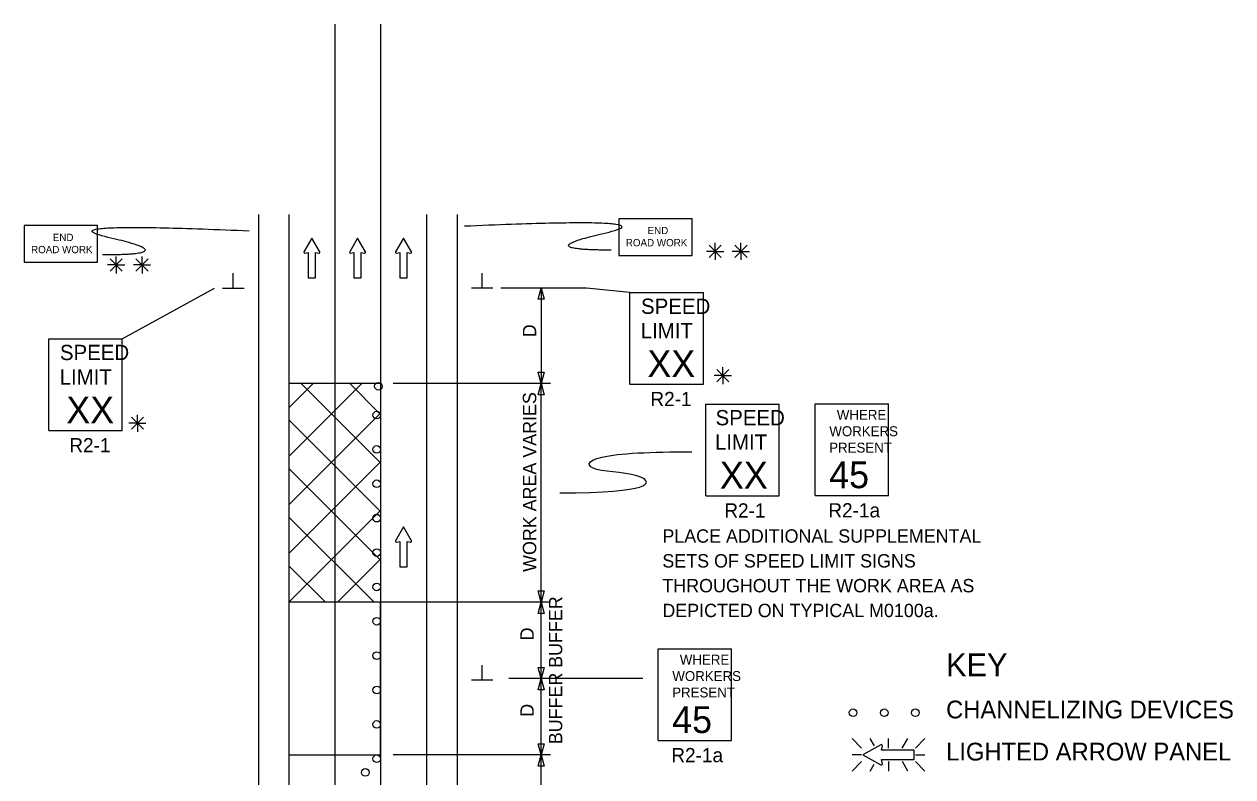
# Model space of a CAD drawing. Extents: x 16553 to 18475, y 5759 to 7026.
# Drawn here: x 16749 to 17382, y 6632 to 7026 of the extents above; entities that cross this region are included whole.
import ezdxf

# ---------------------------------------------------------------- set-up
doc = ezdxf.new("R2010")
doc.units = 0
for name, color, linetype in [('ALI_LEGAL_EX', 7, 'Continuous'), ('MT_SCRATCH_LEVEL_A', 7, 'Continuous'), ('MT_SCRATCH_LEVEL_E', 7, 'Continuous'), ('PAVT_EDGE_EX', 7, 'Continuous'), ('TRAFFIC_SIGNS_PR', 7, 'Continuous'), ('TYPICAL_TEXT_DIMEN_EX', 7, 'Continuous'), ('TYPICAL_TEXT_DIMEN_PR', 7, 'Continuous')]:
    doc.layers.add(name, color=color, linetype=linetype)

msp = doc.modelspace()

# ---------------------------------------------------------------- linework, layer by layer
at = {"layer": 'ALI_LEGAL_EX'}
for p, q in [((16911.66, 7026.35), (16911.66, 6197.16)), ((16935.66, 7026.35), (16935.66, 6197.16)), ((16935.66, 7026.35), (16935.66, 6197.16))]:
    msp.add_line(p, q, dxfattribs=at)
for points in [[(16911.66, 6926.35), (16911.66, 6901.35)], [(16935.66, 6926.35), (16935.66, 6901.35)], [(16911.66, 6826.35), (16911.66, 6801.35)], [(16935.66, 6826.35), (16935.66, 6801.35)], [(16911.66, 6726.35), (16911.66, 6701.35)], [(16935.66, 6726.35), (16935.66, 6701.35)]]:
    msp.add_lwpolyline(points, dxfattribs=at)
at = {"layer": 'MT_SCRATCH_LEVEL_A'}
msp.add_line((16935.66, 6838.16), (16887.66, 6838.16), dxfattribs=at)
at = {"layer": 'MT_SCRATCH_LEVEL_E'}
for p, q in [((16899.66, 6914.3), (16895.55, 6907.06)), ((16903.81, 6907.06), (16899.66, 6914.3)), ((16923.57, 6914.3), (16919.46, 6907.06)), ((16927.71, 6907.06), (16923.57, 6914.3)), ((16947.62, 6914.3), (16943.51, 6907.06)), ((16951.77, 6907.06), (16947.62, 6914.3)), ((16896.03, 6906.37), (16897.81, 6906.69)), ((16897.81, 6906.69), (16897.81, 6893.43)), ((16901.55, 6893.43), (16901.55, 6906.69)), ((16901.55, 6906.69), (16903.33, 6906.37)), ((16919.94, 6906.37), (16921.72, 6906.69)), ((16921.72, 6906.69), (16921.72, 6893.43)), ((16925.46, 6893.43), (16925.46, 6906.69)), ((16925.46, 6906.69), (16927.23, 6906.37)), ((16943.99, 6906.37), (16945.77, 6906.69)), ((16945.77, 6906.69), (16945.77, 6893.43)), ((16949.51, 6893.43), (16949.51, 6906.69)), ((16949.51, 6906.69), (16951.29, 6906.37)), ((16897.81, 6893.43), (16901.55, 6893.43)), ((16921.72, 6893.43), (16925.46, 6893.43)), ((16945.77, 6893.43), (16949.51, 6893.43)), ((16947.62, 6763.02), (16943.51, 6755.78)), ((16951.77, 6755.78), (16947.62, 6763.02)), ((16943.99, 6755.1), (16945.77, 6755.41)), ((16945.77, 6755.41), (16945.77, 6742.15)), ((16949.51, 6742.15), (16949.51, 6755.41)), ((16949.51, 6755.41), (16951.29, 6755.1)), ((16945.77, 6742.15), (16949.51, 6742.15))]:
    msp.add_line(p, q, dxfattribs=at)
for centre, start, end in [((16895.96, 6906.83), 150.42484, 279.96381), ((16903.4, 6906.83), 260.03619, 29.77312), ((16919.86, 6906.83), 150.42484, 279.96381), ((16927.3, 6906.83), 260.03619, 29.77312), ((16943.92, 6906.83), 150.42484, 279.96381), ((16951.36, 6906.83), 260.03619, 29.77312), ((16943.92, 6755.56), 150.42484, 279.96381), ((16951.36, 6755.56), 260.03619, 29.77312)]:
    msp.add_arc(centre, 0.463, start, end, dxfattribs=at)
at = {"layer": 'PAVT_EDGE_EX'}
for p, q in [((16871.66, 6926.66), (16871.66, 6280.21)), ((16887.66, 6926.66), (16887.66, 6280.21)), ((16959.66, 6926.66), (16959.66, 6280.21)), ((16975.66, 6926.66), (16975.66, 6280.21)), ((16935.66, 6838.16), (16887.66, 6838.16)), ((16887.66, 6838.16), (16887.66, 6723.62)), ((16887.66, 6825.45), (16900.38, 6838.16)), ((16887.66, 6799.99), (16925.83, 6838.16)), ((16935.66, 6796.54), (16894.04, 6838.16)), ((16935.66, 6822), (16919.5, 6838.16)), ((16887.66, 6774.54), (16935.66, 6822.54)), ((16935.66, 6771.08), (16887.66, 6819.08)), ((16887.66, 6749.08), (16935.66, 6797.08)), ((16935.66, 6745.63), (16887.66, 6793.63)), ((16887.66, 6723.62), (16935.66, 6771.62)), ((16932.21, 6723.62), (16887.66, 6768.17)), ((16913.12, 6723.62), (16935.66, 6746.17)), ((16906.76, 6723.62), (16887.66, 6742.72)), ((16887.66, 6643.62), (16935.66, 6643.62))]:
    msp.add_line(p, q, dxfattribs=at)
msp.add_lwpolyline([(16935.66, 6723.62), (16887.66, 6723.62), (16887.66, 6643.62), (16935.66, 6643.62)], close=True, dxfattribs=at)
at = {"layer": 'TRAFFIC_SIGNS_PR'}
for p, q in [((17066.18, 6885.75), (17104.58, 6885.75)), ((17066.18, 6837.75), (17066.18, 6885.75)), ((17104.58, 6837.75), (17104.58, 6885.75)), ((16762.02, 6861.55), (16800.42, 6861.55)), ((16762.02, 6813.55), (16762.02, 6861.55)), ((16800.42, 6813.55), (16800.42, 6861.55)), ((17066.18, 6837.75), (17104.58, 6837.75)), ((17105.94, 6827.39), (17144.34, 6827.39)), ((17105.94, 6779.39), (17105.94, 6827.39)), ((17144.34, 6779.39), (17144.34, 6827.39)), ((17163.13, 6827.47), (17201.53, 6827.47)), ((17163.13, 6779.47), (17163.13, 6827.47)), ((17201.53, 6779.47), (17201.53, 6827.47)), ((16762.02, 6813.55), (16800.42, 6813.55)), ((17105.94, 6779.39), (17144.34, 6779.39)), ((17163.13, 6779.47), (17201.53, 6779.47)), ((17080.96, 6699.25), (17119.36, 6699.25)), ((17080.96, 6651.25), (17080.96, 6699.25)), ((17119.36, 6651.25), (17119.36, 6699.25)), ((17080.96, 6651.25), (17119.36, 6651.25)), ((17182.39, 6652.17), (17187.32, 6647.24)), ((17194.15, 6648.35), (17191.94, 6652.17)), ((17201.47, 6647.24), (17201.47, 6652.17)), ((17208.7, 6647.24), (17211.55, 6652.17)), ((17215.62, 6647.24), (17220.55, 6652.17)), ((17187.32, 6643.68), (17182.39, 6643.68)), ((17215.62, 6643.68), (17220.55, 6643.68)), ((17182.39, 6635.19), (17187.32, 6640.13)), ((17191.9, 6635.19), (17194.01, 6638.85)), ((17201.47, 6640.13), (17201.47, 6635.19)), ((17211.6, 6635.19), (17208.75, 6640.13)), ((17215.62, 6640.13), (17220.55, 6635.19))]:
    msp.add_line(p, q, dxfattribs=at)
for points in [[(17060.4, 6905.24), (17098.8, 6905.24), (17098.8, 6924.44), (17060.4, 6924.44)], [(16749.09, 6901.65), (16787.49, 6901.65), (16787.49, 6920.85), (16749.09, 6920.85)]]:
    msp.add_lwpolyline(points, close=True, dxfattribs=at)
for points in [[(17197.4, 6648.96), (17188.1, 6643.68), (17197.4, 6638.36)], [(17198.27, 6638.99), (17197.87, 6641.26), (17214.88, 6641.26), (17214.88, 6646.06), (17197.87, 6646.06), (17198.27, 6648.34)]]:
    msp.add_lwpolyline(points, dxfattribs=at)
for centre in [(16934.48, 6836.73), (16933.66, 6821.62), (16933.66, 6803.62), (16933.66, 6785.62), (16933.66, 6767.62), (16933.66, 6749.62), (16933.66, 6731.62), (16933.66, 6713.62), (16933.66, 6695.62), (16933.66, 6677.62), (16933.66, 6659.62), (17182.95, 6665.71), (17199.25, 6665.71), (17215.55, 6665.71), (16933.66, 6641.62), (16927.66, 6634.48)]:
    msp.add_circle(centre, 2, dxfattribs=at)
for centre, radius, start, end in [((17197.68, 6648.43), 0.598, 350.73078, 118.89165), ((17197.68, 6638.88), 0.597, 241.48329, 9.95933)]:
    msp.add_arc(centre, radius, start, end, dxfattribs=at)
for points in [[(17056.4, 6908), (17013.89, 6908), (17090.41, 6925.41), (16979.62, 6920.47)], [(16790.14, 6905.64), (16832.65, 6905.64), (16756.13, 6923.05), (16866.92, 6918.11)]]:
    msp.add_open_spline(points, degree=2, dxfattribs=at)
at = {"layer": 'TYPICAL_TEXT_DIMEN_PR'}
for p, q in [((17107.55, 6910.56), (17113.93, 6904.18)), ((17113.93, 6910.56), (17107.55, 6904.18)), ((17110.74, 6907.37), (17110.74, 6911.82)), ((17121.06, 6910.56), (17127.43, 6904.18)), ((17127.43, 6910.56), (17121.06, 6904.18)), ((17124.24, 6907.37), (17124.24, 6911.82)), ((16794.08, 6903.41), (16800.45, 6897.03)), ((16800.45, 6903.41), (16794.08, 6897.03)), ((16797.26, 6900.22), (16797.26, 6904.68)), ((16807.58, 6903.41), (16813.96, 6897.03)), ((16813.96, 6903.41), (16807.58, 6897.03)), ((16810.77, 6900.22), (16810.77, 6904.68)), ((17110.74, 6907.37), (17106.21, 6907.37)), ((17110.74, 6907.37), (17113.93, 6907.37)), ((17110.74, 6907.37), (17115.22, 6907.37)), ((17110.74, 6907.37), (17110.74, 6902.87)), ((17124.24, 6907.37), (17119.71, 6907.37)), ((17124.24, 6907.37), (17127.43, 6907.37)), ((17124.24, 6907.37), (17128.72, 6907.37)), ((17124.24, 6907.37), (17124.24, 6902.87)), ((16797.26, 6900.22), (16792.73, 6900.22)), ((16797.26, 6900.22), (16800.45, 6900.22)), ((16797.26, 6900.22), (16801.74, 6900.22)), ((16797.26, 6900.22), (16797.26, 6895.72)), ((16810.77, 6900.22), (16806.24, 6900.22)), ((16810.77, 6900.22), (16813.96, 6900.22)), ((16810.77, 6900.22), (16815.25, 6900.22)), ((16810.77, 6900.22), (16810.77, 6895.72)), ((16858.54, 6888.16), (16858.54, 6895.95)), ((16988.79, 6888.16), (16988.79, 6895.95)), ((16800.42, 6861.55), (16848.66, 6888.16)), ((16852.91, 6888.16), (16864.16, 6888.16)), ((16994.41, 6888.16), (16983.16, 6888.16)), ((17043.4, 6888.16), (16998.66, 6888.16)), ((17018.09, 6882.3), (17019.66, 6888.16)), ((17019.66, 6888.16), (17019.66, 6838.16)), ((17019.66, 6888.16), (17021.23, 6882.3)), ((17066.18, 6885.75), (17043.4, 6888.16)), ((17019.66, 6882.3), (17018.09, 6882.3)), ((17021.23, 6882.3), (17019.66, 6882.3)), ((17111.6, 6845.45), (17117.97, 6839.07)), ((17117.97, 6845.45), (17111.6, 6839.07)), ((17114.79, 6842.26), (17114.79, 6846.71)), ((17019.66, 6838.16), (17018.09, 6844.02)), ((17018.09, 6844.02), (17019.66, 6844.02)), ((17019.66, 6844.02), (17021.23, 6844.02)), ((17021.23, 6844.02), (17019.66, 6838.16)), ((17114.79, 6842.26), (17110.26, 6842.26)), ((17114.79, 6842.26), (17117.97, 6842.26)), ((17114.79, 6842.26), (17119.26, 6842.26)), ((17114.79, 6842.26), (17114.79, 6837.76)), ((17024.66, 6838.16), (16942.27, 6838.16)), ((17018.09, 6832.3), (17019.66, 6838.16)), ((17019.66, 6723.62), (17019.66, 6838.16)), ((17019.66, 6838.16), (17021.23, 6832.3)), ((17019.66, 6832.3), (17018.09, 6832.3)), ((17021.23, 6832.3), (17019.66, 6832.3)), ((16805.19, 6820.53), (16811.56, 6814.15)), ((16811.56, 6820.53), (16805.19, 6814.15)), ((16808.38, 6817.34), (16808.38, 6821.8)), ((16808.38, 6817.34), (16803.84, 6817.34)), ((16808.38, 6817.34), (16811.56, 6817.34)), ((16808.38, 6817.34), (16812.85, 6817.34)), ((16808.38, 6817.34), (16808.38, 6812.84)), ((17019.66, 6723.62), (17018.09, 6729.49)), ((17018.09, 6729.49), (17019.66, 6729.49)), ((17019.66, 6729.49), (17021.23, 6729.49)), ((17021.23, 6729.49), (17019.66, 6723.62)), ((17024.66, 6723.62), (16935.66, 6723.62)), ((17018.09, 6717.76), (17019.66, 6723.62)), ((17019.66, 6683.62), (17019.66, 6723.62)), ((17019.66, 6723.62), (17021.23, 6717.76)), ((17019.66, 6717.76), (17018.09, 6717.76)), ((17021.23, 6717.76), (17019.66, 6717.76)), ((16988.79, 6682.78), (16988.79, 6690.56)), ((17019.66, 6683.62), (17018.09, 6689.49)), ((17018.09, 6689.49), (17019.66, 6689.49)), ((17019.66, 6689.49), (17021.23, 6689.49)), ((17021.23, 6689.49), (17019.66, 6683.62)), ((16994.41, 6682.78), (16983.16, 6682.78)), ((17072.97, 6683.62), (17002.68, 6683.62)), ((17018.09, 6677.76), (17019.66, 6683.62)), ((17019.66, 6643.62), (17019.66, 6683.62)), ((17019.66, 6683.62), (17021.23, 6677.76)), ((17019.66, 6677.76), (17018.09, 6677.76)), ((17021.23, 6677.76), (17019.66, 6677.76)), ((17019.66, 6643.62), (17018.09, 6649.49)), ((17018.09, 6649.49), (17019.66, 6649.49)), ((17019.66, 6649.49), (17021.23, 6649.49)), ((17021.23, 6649.49), (17019.66, 6643.62)), ((17024.66, 6643.62), (16942.27, 6643.62)), ((17018.09, 6637.76), (17019.66, 6643.62)), ((17019.66, 6613.06), (17019.66, 6643.62)), ((17019.66, 6643.62), (17021.23, 6637.76)), ((17019.66, 6637.76), (17018.09, 6637.76)), ((17021.23, 6637.76), (17019.66, 6637.76))]:
    msp.add_line(p, q, dxfattribs=at)
msp.add_open_spline([(17029.51, 6780.89), (17077.98, 6780.89), (17077.98, 6791.65), (17043.06, 6791.65), (17043.06, 6800.7), (17077.26, 6802.46), (17098.55, 6802.36)], degree=3, dxfattribs=at)

# ---------------------------------------------------------------- texts
at = {"layer": 'TRAFFIC_SIGNS_PR'}
for s, height, p in [('END', 3.831, (16764.09, 6912.77)), ('END', 3.831, (17075.4, 6916.37)), ('ROAD WORK', 3.831, (16752.7, 6906.39)), ('ROAD WORK', 3.831, (17064.01, 6909.99)), ('SPEED', 8, (17071.95, 6874.61)), ('LIMIT', 8, (17071.79, 6861.81)), ('SPEED', 8, (16767.79, 6850.41)), ('XX', 14.031, (17075.29, 6841.51)), ('LIMIT', 8, (16767.63, 6837.61)), ('R2-1', 7.44, (17076.86, 6826.31)), ('XX', 14.031, (16771.14, 6817.31)), ('SPEED', 8, (17110.97, 6816.25)), ('WHERE', 5.2, (17174.44, 6819.16)), ('WORKERS', 5.2, (17170.52, 6810.56)), ('R2-1', 7.44, (16772.7, 6802.11)), ('LIMIT', 8, (17110.64, 6803.45)), ('PRESENT', 5.2, (17170.45, 6801.96)), ('XX', 14.031, (17113.24, 6783.14)), ('45', 14.031, (17170.44, 6783.33)), ('R2-1', 7.44, (17115.55, 6767.95)), ('R2-1a', 7.44, (17169.99, 6768.03)), ('PLACE ADDITIONAL SUPPLEMENTAL', 7, (17083.13, 6754.78)), ('SETS OF SPEED LIMIT SIGNS', 7, (17083.13, 6741.78)), ('THROUGHOUT THE WORK AREA AS', 7, (17083.13, 6728.78)), ('DEPICTED ON TYPICAL M0100a.', 7, (17083.13, 6715.78)), ('WHERE', 5.2, (17092.27, 6690.93)), ('WORKERS', 5.2, (17088.34, 6682.33)), ('PRESENT', 5.2, (17088.27, 6673.73)), ('45', 14.031, (17088.26, 6655.1)), ('R2-1a', 7.44, (17087.81, 6639.81))]:
    msp.add_text(s, height=height, dxfattribs=at).set_placement(p)
at = {"layer": 'TYPICAL_TEXT_DIMEN_EX'}
for s, height, p in [('KEY', 12, (17231.64, 6684.81)), ('CHANNELIZING DEVICES', 9.3, (17231.64, 6662.76)), ('LIGHTED ARROW PANEL', 9.3, (17231.64, 6640.71))]:
    msp.add_text(s, height=height, dxfattribs=at).set_placement(p)
at = {"layer": 'TYPICAL_TEXT_DIMEN_PR'}
for s, p in [('D', (17017.1, 6862.38)), ('WORK AREA VARIES', (17017.1, 6739.48)), ('BUFFER', (17030.73, 6689.25)), ('D', (17015.81, 6703.6)), ('BUFFER', (17030.73, 6649.25)), ('D', (17015.81, 6663.6))]:
    msp.add_text(s, height=7, rotation=90, dxfattribs=at).set_placement(p)

doc.saveas('drawing.dxf')
